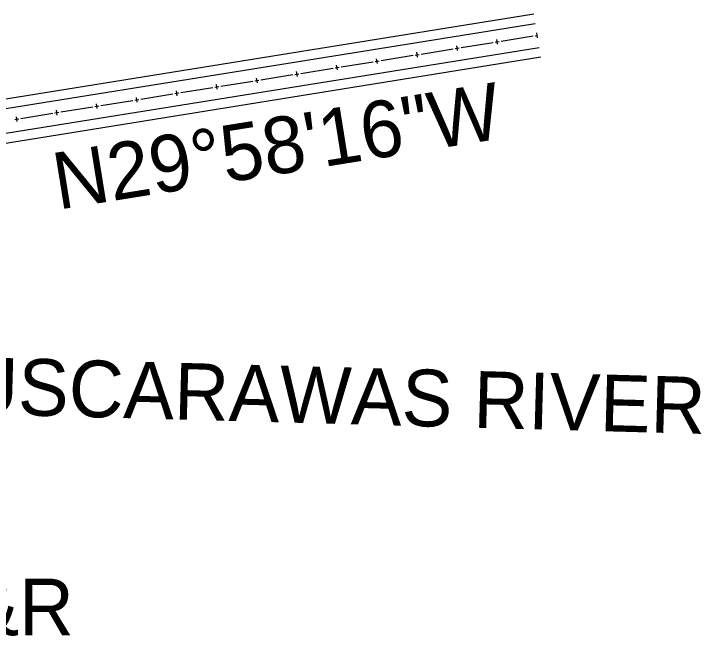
# Model space of a CAD drawing. Extents: x 0 to 34000, y 0 to 22000.
# Drawn here: x 27999 to 29694, y 4850 to 6385 of the extents above; entities that cross this region are included whole.
import ezdxf

# ---------------------------------------------------------------- set-up
doc = ezdxf.new("R2010")
doc.units = 0
doc.layers.add('Default', color=7, linetype='Continuous')
doc.layers.add('GE_P_CL_100', color=7, linetype='Continuous')

msp = doc.modelspace()

# ---------------------------------------------------------------- linework, layer by layer
at = {"layer": 'Default'}
for p, q in [((27010.1, 6019.9), (29281, 6385.3)), ((27013.9, 5996.2), (29284.9, 6361.6)), ((29290.5, 6326), (29288.6, 6337.9)), ((29191.7, 6310.1), (29189.8, 6322)), ((27023.5, 5936.9), (29294.4, 6302.4)), ((28994.3, 6278.4), (28992.4, 6290.2)), ((29093, 6294.3), (29091.1, 6306.1)), ((27027.3, 5913.2), (29298.2, 6278.7)), ((28895.5, 6262.5), (28893.6, 6274.3)), ((28796.8, 6246.6), (28794.9, 6258.4)), ((28698.1, 6230.7), (28696.2, 6242.6)), ((28599.4, 6214.8), (28597.5, 6226.7)), ((28500.6, 6198.9), (28498.7, 6210.8)), ((28401.9, 6183), (28400, 6194.9)), ((28303.2, 6167.2), (28301.3, 6179)), ((28204.5, 6151.3), (28202.5, 6163.1)), ((28098.6, 6140.3), (28098.6, 6140.3)), ((28105.7, 6135.4), (28103.8, 6147.2)), ((28104.8, 6141.3), (28104.8, 6141.3)), ((28007, 6119.5), (28005.1, 6131.3))]:
    msp.add_line(p, q, dxfattribs=at)
for points in [[(29200.7, 6317.6), (29279.6, 6330.4)], [(29284.6, 6331.2), (29289.5, 6331.9)], [(29101.9, 6301.8), (29180.9, 6314.5)], [(29185.9, 6315.3), (29195.7, 6316.9)], [(29003.2, 6285.9), (29082.2, 6298.6)], [(29087.1, 6299.4), (29097, 6301)], [(28904.5, 6270), (28983.5, 6282.7)], [(28988.4, 6283.5), (28998.3, 6285.1)], [(28805.7, 6254.1), (28884.7, 6266.8)], [(28889.7, 6267.6), (28899.5, 6269.2)], [(28707, 6238.2), (28786, 6250.9)], [(28790.9, 6251.7), (28800.8, 6253.3)], [(28608.3, 6222.3), (28687.3, 6235)], [(28692.2, 6235.8), (28702.1, 6237.4)], [(28494.8, 6204.1), (28504.6, 6205.6)], [(28509.6, 6206.4), (28588.5, 6219.1)], [(28593.5, 6219.9), (28603.4, 6221.5)], [(28396, 6188.2), (28405.9, 6189.8)], [(28410.8, 6190.6), (28489.8, 6203.3)], [(28297.3, 6172.3), (28307.2, 6173.9)], [(28312.1, 6174.7), (28391.1, 6187.4)], [(28114.6, 6142.9), (28193.6, 6155.6)], [(28198.6, 6156.4), (28208.4, 6158)], [(28213.4, 6158.8), (28292.4, 6171.5)], [(28015.9, 6127), (28094.9, 6139.7)], [(28099.8, 6140.5), (28109.7, 6142.1)], [(28001.1, 6124.6), (28011, 6126.2)]]:
    msp.add_lwpolyline(points, dxfattribs=at)

# ---------------------------------------------------------------- texts
at = {"layer": 'GE_P_CL_100'}
for s, rotation, p in [('N29°58\'16"W', 9.1414, (28108.1, 5901.7)), ('TUSCARAWAS RIVER', 358.4259, (27758.4, 5401.9))]:
    msp.add_text(s, height=140, rotation=rotation, dxfattribs=at).set_placement(p)
msp.add_text('TUS-00077-03.880 L&R', height=140, dxfattribs=at).set_placement((26138.4, 4851.5))

doc.saveas('drawing.dxf')
